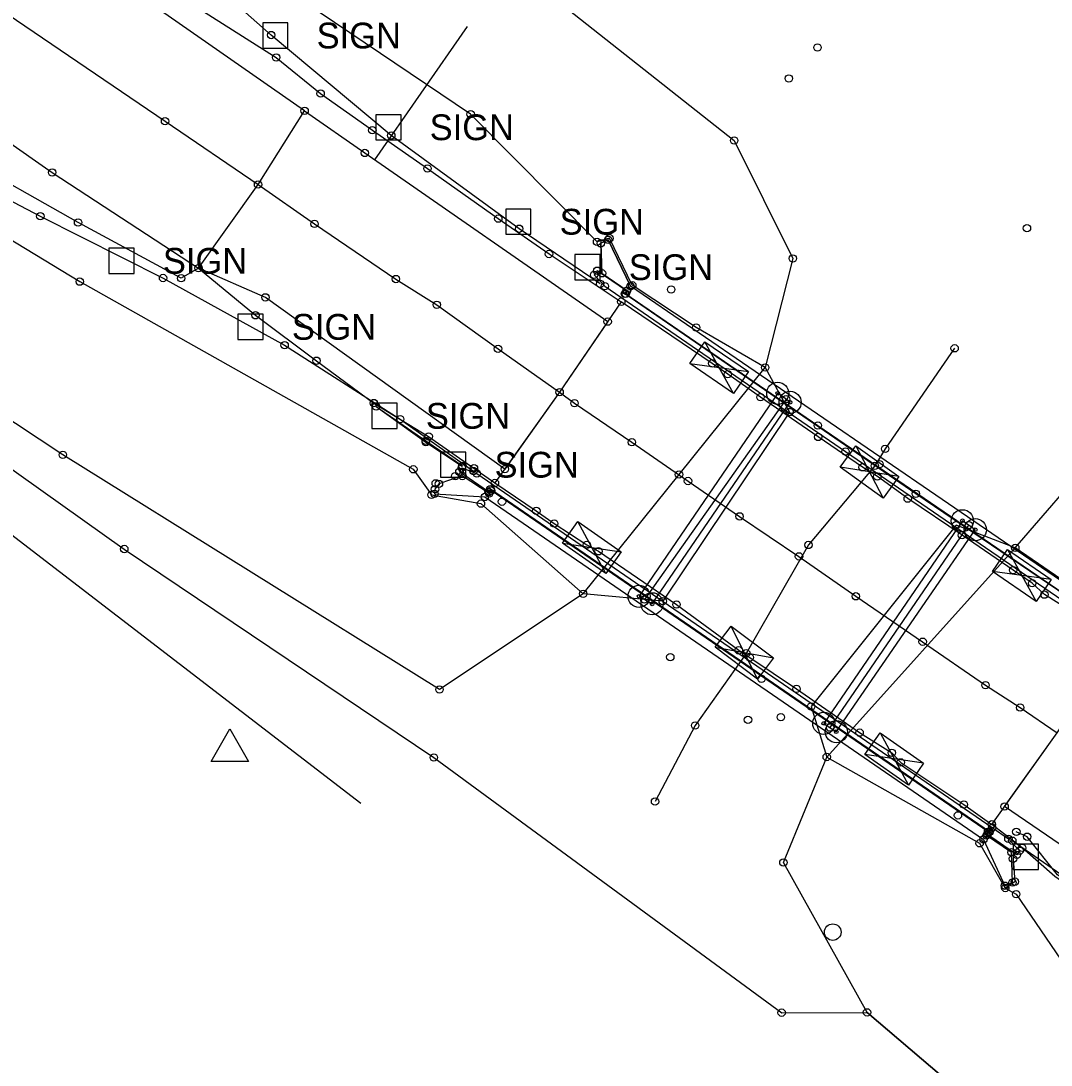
# Model space of a CAD drawing. Extents: x 15502398 to 15534190, y 8766930 to 8782112.
# Drawn here: x 15514814.8 to 15514954.6, y 8779044.6 to 8779186.3 of the extents above; entities that cross this region are included whole.
import ezdxf

# ---------------------------------------------------------------- set-up
doc = ezdxf.new("R2010")
doc.units = 0
for name, color, linetype in [('Bridge', 7, 'Continuous'), ('Default', 7, 'Continuous'), ('EXT_BL', 7, 'Continuous'), ('EXT_C', 7, 'Continuous'), ('EXT_CON', 7, 'Continuous'), ('EXT_CU', 7, 'Continuous'), ('EXT_D', 7, 'Continuous'), ('EXT_EP', 7, 'Continuous'), ('EXT_GU', 7, 'Continuous'), ('EXT_SH', 7, 'Continuous'), ('EXT_SNP', 7, 'Continuous'), ('Natural', 7, 'Continuous'), ('Roadways', 7, 'Continuous'), ('SurControl', 7, 'Continuous'), ('SurPointsNonDTM', 7, 'Continuous'), ('SurRoadPoints', 7, 'Continuous'), ('SurSurveyPoints', 7, 'Continuous'), ('SurUtilityStructureCell', 7, 'Continuous')]:
    doc.layers.add(name, color=color, linetype=linetype)

msp = doc.modelspace()

# ---------------------------------------------------------------- linework, layer by layer
at = {"layer": 'Bridge'}
for points in [[(15514968.75, 8779100.6), (15514969.07, 8779101.28), (15514971.97, 8779101.81), (15514972.1, 8779103.31), (15514965.17, 8779103.99), (15514897.53, 8779150.29), (15514894.5, 8779156.59), (15514893.48, 8779156.12), (15514893.65, 8779152.05), (15514897.07, 8779149.71), (15514896.88, 8779149.26), (15514922.95, 8779131.4), (15514964.36, 8779103.05), (15514964.63, 8779103.39)], [(15514968.68, 8779100.45), (15514964.72, 8779103.21), (15514964.5, 8779102.92), (15514936.22, 8779122.13), (15514896.74, 8779149.27), (15514896.98, 8779149.65), (15514892.99, 8779152.4), (15514892.59, 8779151.84), (15514894.03, 8779150.29), (15514926.69, 8779127.87), (15514966.4, 8779100.62), (15514968.22, 8779099.97)], [(15514949.95, 8779073.12), (15514945.97, 8779075.89), (15514946.23, 8779076.23), (15514878.5, 8779122.74), (15514878.27, 8779122.37), (15514874.3, 8779125.1), (15514874.64, 8779125.67), (15514876.68, 8779124.87), (15514946.6, 8779076.81), (15514948.79, 8779075.28), (15514950.32, 8779073.68)], [(15514949.36, 8779069.37), (15514949.21, 8779073.46), (15514945.82, 8779075.74), (15514946.03, 8779076.25), (15514878.6, 8779122.55), (15514878.34, 8779122.17), (15514874.7, 8779124.54), (15514871.53, 8779123.48), (15514870.99, 8779122.75), (15514870.92, 8779122.12), (15514877.75, 8779121.69), (15514945.42, 8779075.22), (15514948.31, 8779068.93)]]:
    msp.add_lwpolyline(points, close=True, dxfattribs=at)
at = {"layer": 'Default'}
for points in [[(15514893.39, 8779150.63), (15514882.42, 8779158.1), (15514865.06, 8779170.76), (15514848.76, 8779184.39), (15514828.98, 8779201.9)], [(15514805.39, 8779167.3), (15514804.8, 8779166.43), (15514817.44, 8779159.8), (15514834.09, 8779151.41), (15514850.59, 8779142.29), (15514866.26, 8779132.25), (15514876.21, 8779125.21)], [(15514960.76, 8779104.04), (15514953.68, 8779108.44), (15514952.01, 8779109.98), (15514949.45, 8779111.77), (15514942.5, 8779116.5), (15514935.13, 8779121.47), (15514931.01, 8779124.47), (15514929.01, 8779125.72), (15514922.98, 8779129.84), (15514915.15, 8779135.23), (15514910.73, 8779138.36), (15514908.62, 8779139.83), (15514896.27, 8779148.2), (15514887.9, 8779135.92), (15514879.13, 8779123.59)], [(15514887.9, 8779135.92), (15514889.92, 8779134.43), (15514897.71, 8779129.12), (15514905.32, 8779123.86), (15514912.32, 8779119.06), (15514920.38, 8779113.63), (15514928.09, 8779108.21), (15514937.16, 8779102.05), (15514945.69, 8779096.15), (15514950.38, 8779093.11), (15514955.43, 8779089.67)], [(15514918.63, 8779134.96), (15514899.4, 8779107.78)], [(15514876.28, 8779125.6), (15514879.13, 8779123.59), (15514884.74, 8779119.8), (15514887.17, 8779118.08), (15514891.59, 8779115.19), (15514893.17, 8779114.32), (15514903.77, 8779107.09), (15514912.2, 8779100.88), (15514913.72, 8779099.91), (15514920.05, 8779095.64), (15514928.61, 8779089.71), (15514932.97, 8779086.98), (15514934.18, 8779085.67), (15514942.74, 8779079.94), (15514946.55, 8779077.26), (15514955.43, 8779089.67)], [(15514924.6, 8779090.39), (15514943.43, 8779117.86)], [(15515014.78, 8779024.91), (15515014.27, 8779023.91), (15514993.78, 8779041.38), (15514983.04, 8779050.29), (15514963.22, 8779065.38), (15514949.32, 8779075.04)]]:
    msp.add_lwpolyline(points, dxfattribs=at)
for points in [[(15514900.45, 8779107.19), (15514919.18, 8779134.54), (15514917.5, 8779135.76), (15514898.68, 8779108.21)], [(15514944.3, 8779117.25), (15514942.55, 8779118.46), (15514923.75, 8779090.97), (15514925.44, 8779089.82)]]:
    msp.add_lwpolyline(points, close=True, dxfattribs=at)
at = {"layer": 'EXT_BL'}
for points in [[(15514603.51, 8779232.29), (15514601.83, 8779245.57), (15514595.97, 8779254.75), (15514571.89, 8779280.15), (15514580.49, 8779291.91), (15514600.21, 8779303.93), (15514639.34, 8779277.58), (15514691.14, 8779242.93), (15514735.8, 8779211.77), (15514779.77, 8779177.06), (15514822.79, 8779150.92), (15514868.05, 8779125.45), (15514870.51, 8779121.99), (15514877.23, 8779120.79), (15514891.1, 8779108.56)], [(15514891.1, 8779108.56), (15514871.59, 8779095.57), (15514820.49, 8779127.42), (15514785.11, 8779150.78), (15514725.93, 8779192.76), (15514674.35, 8779232.07), (15514625.56, 8779268.53), (15514604.03, 8779280.96), (15514600.16, 8779276.05), (15514595.07, 8779269.61), (15514606.22, 8779257.75), (15514613.46, 8779244.67), (15514610.28, 8779231.05)], [(15514797.21, 8779253.2), (15514839.32, 8779228.6), (15514874.17, 8779199.67), (15514911.58, 8779170.08), (15514919.55, 8779154.07), (15514915.79, 8779139.27), (15514906.42, 8779144.7), (15514897.76, 8779150.42), (15514894.68, 8779156.8), (15514892.98, 8779156.33), (15514875.83, 8779173.65), (15514853.31, 8779188.82), (15514802.74, 8779223.63)], [(15514941.5, 8779141.87), (15514932.06, 8779128.22), (15514930.67, 8779125.91), (15514921.66, 8779115.18), (15514913.23, 8779100.47), (15514906.3, 8779090.67), (15514900.85, 8779080.35)], [(15514891.1, 8779108.56), (15514904.1, 8779124.74), (15514915.79, 8779139.27)], [(15514915.79, 8779139.27), (15514919.11, 8779133.22), (15514901.89, 8779107.55), (15514891.1, 8779108.56)], [(15514972.37, 8779103.34), (15514965.29, 8779104.12), (15514949.73, 8779114.8), (15514960.51, 8779127.28), (15514971.69, 8779129.58), (15515012.98, 8779104.1), (15515039.09, 8779087.26), (15515084.34, 8779057.54), (15515121.87, 8779031.85), (15515136.34, 8779033.05), (15515158.53, 8779017.54), (15515157.87, 8778999.81), (15515198.39, 8778971.5), (15515237.86, 8778943.51), (15515264.4, 8778926.3), (15515290.1, 8778939.84)], [(15514949.73, 8779114.8), (15514941.69, 8779117.88), (15514922.03, 8779093.25), (15514924.14, 8779086.4)], [(15514924.14, 8779086.4), (15514949.73, 8779114.8)], [(15515236.34, 8778829.26), (15515147, 8778893.37), (15515095.71, 8778929.07), (15515036.69, 8778970.82), (15514983.06, 8779009.89), (15514945.58, 8779038.12), (15514929.61, 8779051.74), (15514918.26, 8779072.09), (15514924.14, 8779086.4)], [(15514924.14, 8779086.4), (15514944.89, 8779074.69), (15514948.37, 8779068.62), (15514949.86, 8779067.79), (15514955.86, 8779058.94), (15515004.6, 8779026.01), (15515051.74, 8778995.2), (15515103.32, 8778961.08), (15515168.39, 8778915.34), (15515228.98, 8778873.25), (15515256.8, 8778852.96)], [(15514949.42, 8779072.59), (15514949.68, 8779069.48), (15514948.37, 8779068.62)]]:
    msp.add_lwpolyline(points, dxfattribs=at)
at = {"layer": 'EXT_C'}
msp.add_lwpolyline([(15514539.01, 8779375.88), (15514557.84, 8779363.02), (15514577.62, 8779349.14), (15514597.39, 8779335.77), (15514617.16, 8779321.93), (15514638.22, 8779307.5), (15514657.64, 8779293.96), (15514678.58, 8779279.44), (15514697.02, 8779266.72), (15514717.08, 8779253.14), (15514730.81, 8779243.96), (15514754.17, 8779227.88), (15514774.39, 8779213.87), (15514794.54, 8779199.93), (15514814.21, 8779186.39), (15514834.36, 8779172.7), (15514846.98, 8779164.09), (15514854.64, 8779158.75), (15514865.69, 8779151.27), (15514871.23, 8779147.78), (15514879.54, 8779141.8), (15514887.9, 8779135.92)], dxfattribs=at)
at = {"layer": 'EXT_CON'}
for points in [[(15514893.65, 8779152.05), (15514893.48, 8779156.12), (15514894.5, 8779156.59), (15514897.53, 8779150.29)], [(15514874.7, 8779124.54), (15514871.53, 8779123.48), (15514870.99, 8779122.75), (15514870.92, 8779122.12), (15514877.75, 8779121.69)], [(15514945.42, 8779075.22), (15514948.31, 8779068.93), (15514949.36, 8779069.37), (15514949.21, 8779073.46)]]:
    msp.add_lwpolyline(points, dxfattribs=at)
at = {"layer": 'EXT_CU'}
for points in [[(15514863.02, 8779133.97), (15514869.76, 8779129.13), (15514874.67, 8779125.88)], [(15514962.8, 8779065.26), (15514961.63, 8779065.61), (15514955.09, 8779070.17), (15514950.65, 8779074.06), (15514946.55, 8779077.26)]]:
    msp.add_lwpolyline(points, dxfattribs=at)
at = {"layer": 'EXT_D'}
for p, q in [((15514642.88, 8779247.59), (15514860.95, 8779080.15)), ((15514862.83, 8779167.44), (15514875.41, 8779185.56))]:
    msp.add_line(p, q, dxfattribs=at)
at = {"layer": 'EXT_EP'}
for points in [[(15514853.3, 8779174.1), (15514834.8, 8779187), (15514799.88, 8779210.74), (15514777.73, 8779226.07), (15514758.94, 8779238.88), (15514760.07, 8779239.95)], [(15514798.13, 8779180.33), (15514819.06, 8779165.74), (15514838.9, 8779152.76)], [(15514838.9, 8779152.76), (15514846.63, 8779146.35), (15514854.91, 8779140.19), (15514862.7, 8779134.44), (15514870.13, 8779129.91), (15514879.13, 8779123.59)]]:
    msp.add_lwpolyline(points, dxfattribs=at)
at = {"layer": 'EXT_GU'}
for points in [[(15514863.02, 8779133.97), (15514869.73, 8779129.32), (15514874.72, 8779125.91), (15514874.67, 8779125.88)], [(15514962.8, 8779065.26), (15514962.15, 8779065.84), (15514955.44, 8779070.43), (15514951.34, 8779075.58), (15514949.87, 8779076.25)]]:
    msp.add_lwpolyline(points, dxfattribs=at)
at = {"layer": 'EXT_SH'}
msp.add_lwpolyline([(15514809.56, 8779207.33), (15514816.96, 8779202.78), (15514833.52, 8779191.48), (15514849.45, 8779181.35), (15514855.47, 8779176.44), (15514862.49, 8779171.48), (15514869.96, 8779166.28), (15514879.58, 8779159.47), (15514886.46, 8779154.67), (15514896.27, 8779148.2)], dxfattribs=at)
at = {"layer": 'EXT_SNP'}
msp.add_lwpolyline([(15514838.9, 8779152.76), (15514836.55, 8779151.38), (15514822.56, 8779158.95), (15514806.37, 8779168.08), (15514787.02, 8779180.21), (15514762.57, 8779195.1), (15514715.8, 8779227.37), (15514667.65, 8779260.24), (15514628.46, 8779287.04), (15514585.22, 8779314.14)], dxfattribs=at)
at = {"layer": 'Natural'}
msp.add_lwpolyline([(15514714.5, 8779119.23), (15514742.47, 8779138.72), (15514734.07, 8779166.12), (15514775.23, 8779152.76), (15514828.83, 8779114.63), (15514870.83, 8779086.34), (15514918.03, 8779051.7), (15514929.61, 8779051.74), (15514945.58, 8779038.12), (15514983.06, 8779009.89), (15515036.69, 8778970.82), (15515087.59, 8778922.26), (15515066.58, 8778890.05)], dxfattribs=at)
at = {"layer": 'Roadways'}
for points in [[(15514894.42, 8779145.49), (15514887.9, 8779135.92), (15514880.47, 8779125.48), (15514847.98, 8779148.78), (15514838.9, 8779152.76), (15514846.98, 8779164.09), (15514853.3, 8779174.1), (15514861.47, 8779168.38)], [(15515004, 8779071.19), (15514996.44, 8779061.55), (15514989.57, 8779051.49), (15514981.33, 8779057.12), (15514948.28, 8779079.67), (15514955.43, 8779089.67), (15514961.79, 8779099.09), (15514994.98, 8779076.8)]]:
    msp.add_lwpolyline(points, close=True, dxfattribs=at)
at = {"layer": 'SurControl'}
msp.add_lwpolyline([(15514843.16, 8779090.22), (15514845.7, 8779085.81), (15514840.61, 8779085.81)], close=True, dxfattribs=at)
msp.add_circle((15514924.96, 8779062.63), 1.12, dxfattribs=at)
at = {"layer": 'SurPointsNonDTM'}
for centre in [(15514848.76, 8779184.39), (15514853.3, 8779174.1), (15514865.06, 8779170.76), (15514861.47, 8779168.38), (15514846.98, 8779164.09), (15514817.44, 8779159.8), (15514882.42, 8779158.1), (15514893.48, 8779156.12), (15514894.5, 8779156.59), (15514838.9, 8779152.76), (15514892.59, 8779151.84), (15514892.99, 8779152.4), (15514893.65, 8779152.05), (15514834.09, 8779151.41), (15514893.39, 8779150.63), (15514894.03, 8779150.29), (15514897.53, 8779150.29), (15514847.98, 8779148.78), (15514896.74, 8779149.27), (15514896.88, 8779149.26), (15514896.98, 8779149.65), (15514897.07, 8779149.71), (15514903.03, 8779149.86), (15514896.27, 8779148.2), (15514894.42, 8779145.49), (15514894.42, 8779145.49), (15514850.59, 8779142.29), (15514908.62, 8779139.83), (15514910.73, 8779138.36), (15514887.9, 8779135.92), (15514887.9, 8779135.92), (15514887.9, 8779135.92), (15514915.15, 8779135.23), (15514918.63, 8779134.96), (15514889.92, 8779134.43), (15514866.26, 8779132.25), (15514922.95, 8779131.4), (15514897.71, 8779129.12), (15514922.98, 8779129.84), (15514926.69, 8779127.87), (15514931.31, 8779126.15), (15514874.3, 8779125.1), (15514874.64, 8779125.67), (15514876.21, 8779125.21), (15514876.28, 8779125.6), (15514876.68, 8779124.87), (15514880.47, 8779125.48), (15514929.01, 8779125.72), (15514871.53, 8779123.48), (15514874.7, 8779124.54), (15514879.13, 8779123.59), (15514879.13, 8779123.59), (15514905.32, 8779123.86), (15514931.01, 8779124.47), (15514870.92, 8779122.12), (15514870.99, 8779122.75), (15514878.27, 8779122.37), (15514878.34, 8779122.17), (15514878.5, 8779122.74), (15514878.6, 8779122.55), (15514936.22, 8779122.13), (15514877.75, 8779121.69), (15514880.08, 8779121.05), (15514935.13, 8779121.47), (15514884.74, 8779119.8), (15514912.32, 8779119.06), (15514887.17, 8779118.08), (15514943.43, 8779117.86), (15514942.5, 8779116.5), (15514891.59, 8779115.19), (15514828.83, 8779114.63), (15514893.17, 8779114.32), (15514920.38, 8779113.63), (15514949.45, 8779111.77), (15514952.01, 8779109.98), (15514899.4, 8779107.78), (15514928.09, 8779108.21), (15514953.68, 8779108.44), (15514903.77, 8779107.09), (15514937.16, 8779102.05), (15514912.2, 8779100.88), (15514913.72, 8779099.91), (15514915.28, 8779097.01), (15514920.05, 8779095.64), (15514945.69, 8779096.15), (15514950.38, 8779093.11), (15514924.6, 8779090.39), (15514928.61, 8779089.71), (15514870.83, 8779086.34), (15514932.97, 8779086.98), (15514934.18, 8779085.67), (15514942.74, 8779079.94), (15514948.28, 8779079.67), (15514941.95, 8779078.48), (15514946.55, 8779077.26), (15514946.6, 8779076.81), (15514945.42, 8779075.22), (15514945.82, 8779075.74), (15514945.97, 8779075.89), (15514946.03, 8779076.25), (15514946.23, 8779076.23), (15514948.79, 8779075.28), (15514949.32, 8779075.04), (15514950.32, 8779073.68), (15514949.21, 8779073.46), (15514949.95, 8779073.12), (15514949.95, 8779073.12), (15514949.36, 8779069.37), (15514949.36, 8779069.37), (15514948.31, 8779068.93), (15514918.03, 8779051.7), (15514929.61, 8779051.74)]:
    msp.add_circle(centre, 0.5, dxfattribs=at)
at = {"layer": 'SurRoadPoints'}
for points in [[(15514849.33, 8779182.61), (15514849.33, 8779182.61), (15514851.04, 8779182.61), (15514851.04, 8779186.03), (15514847.62, 8779186.03), (15514847.62, 8779182.61), (15514849.33, 8779182.61)], [(15514864.66, 8779170.16), (15514864.66, 8779170.16), (15514866.38, 8779170.16), (15514866.38, 8779173.58), (15514862.95, 8779173.58), (15514862.95, 8779170.16), (15514864.66, 8779170.16)], [(15514882.3, 8779157.34), (15514882.3, 8779157.34), (15514884.01, 8779157.34), (15514884.01, 8779160.76), (15514880.59, 8779160.76), (15514880.59, 8779157.34), (15514882.3, 8779157.34)], [(15514828.46, 8779152.02), (15514828.46, 8779152.02), (15514830.17, 8779152.02), (15514830.17, 8779155.45), (15514826.75, 8779155.45), (15514826.75, 8779152.02), (15514828.46, 8779152.02)], [(15514891.68, 8779151.16), (15514891.68, 8779151.16), (15514893.39, 8779151.16), (15514893.39, 8779154.59), (15514889.97, 8779154.59), (15514889.97, 8779151.16), (15514891.68, 8779151.16)], [(15514845.96, 8779143.07), (15514845.96, 8779143.07), (15514847.68, 8779143.07), (15514847.68, 8779146.5), (15514844.25, 8779146.5), (15514844.25, 8779143.07), (15514845.96, 8779143.07)], [(15514864.14, 8779130.98), (15514864.14, 8779130.98), (15514865.86, 8779130.98), (15514865.86, 8779134.41), (15514862.43, 8779134.41), (15514862.43, 8779130.98), (15514864.14, 8779130.98)], [(15514873.46, 8779124.36), (15514873.46, 8779124.36), (15514875.17, 8779124.36), (15514875.17, 8779127.79), (15514871.75, 8779127.79), (15514871.75, 8779124.36), (15514873.46, 8779124.36)], [(15514951.15, 8779071.14), (15514951.15, 8779071.14), (15514952.87, 8779071.14), (15514952.87, 8779074.57), (15514949.44, 8779074.57), (15514949.44, 8779071.14), (15514951.15, 8779071.14)]]:
    msp.add_lwpolyline(points, dxfattribs=at)
for centre, radius in [((15514917.5, 8779135.76), 1.5), ((15514917.5, 8779135.76), 0.25), ((15514919.18, 8779134.54), 1.5), ((15514919.18, 8779134.54), 0.25), ((15514942.55, 8779118.46), 1.5), ((15514942.55, 8779118.46), 0.25), ((15514944.3, 8779117.25), 1.5), ((15514944.3, 8779117.25), 1.5), ((15514944.3, 8779117.25), 0.25), ((15514944.3, 8779117.25), 0.25), ((15514898.68, 8779108.21), 1.5), ((15514898.68, 8779108.21), 0.25), ((15514900.45, 8779107.19), 1.5), ((15514900.45, 8779107.19), 1.5), ((15514900.45, 8779107.19), 0.25), ((15514900.45, 8779107.19), 0.25), ((15514923.75, 8779090.97), 1.5), ((15514923.75, 8779090.97), 0.25), ((15514925.44, 8779089.82), 1.5), ((15514925.44, 8779089.82), 0.25)]:
    msp.add_circle(centre, radius, dxfattribs=at)
at = {"layer": 'SurSurveyPoints'}
for centre in [(15514849.45, 8779181.35), (15514922.9, 8779182.69), (15514919, 8779178.5), (15514855.47, 8779176.44), (15514853.3, 8779174.1), (15514875.83, 8779173.65), (15514834.36, 8779172.7), (15514862.49, 8779171.48), (15514911.58, 8779170.08), (15514819.06, 8779165.74), (15514869.96, 8779166.28), (15514846.98, 8779164.09), (15514822.56, 8779158.95), (15514854.64, 8779158.75), (15514879.58, 8779159.47), (15514951.31, 8779158.17), (15514892.98, 8779156.33), (15514893.48, 8779156.12), (15514894.5, 8779156.59), (15514894.68, 8779156.8), (15514886.46, 8779154.67), (15514919.55, 8779154.07), (15514838.9, 8779152.76), (15514838.9, 8779152.76), (15514838.9, 8779152.76), (15514893.65, 8779152.05), (15514822.79, 8779150.92), (15514836.55, 8779151.38), (15514865.69, 8779151.27), (15514897.53, 8779150.29), (15514897.76, 8779150.42), (15514871.23, 8779147.78), (15514896.27, 8779148.2), (15514846.63, 8779146.35), (15514906.42, 8779144.7), (15514879.54, 8779141.8), (15514941.5, 8779141.87), (15514854.91, 8779140.19), (15514915.79, 8779139.27), (15514915.79, 8779139.27), (15514915.79, 8779139.27), (15514887.9, 8779135.92), (15514862.7, 8779134.44), (15514863.02, 8779133.97), (15514863.02, 8779133.97), (15514919.11, 8779133.22), (15514869.73, 8779129.32), (15514869.76, 8779129.13), (15514870.13, 8779129.91), (15514932.06, 8779128.22), (15514820.49, 8779127.42), (15514868.05, 8779125.45), (15514874.67, 8779125.88), (15514874.67, 8779125.88), (15514874.72, 8779125.91), (15514904.1, 8779124.74), (15514930.67, 8779125.91), (15514871.09, 8779123.54), (15514871.53, 8779123.48), (15514873.74, 8779124.52), (15514874.7, 8779124.54), (15514879.13, 8779123.59), (15514870.51, 8779121.99), (15514870.92, 8779122.12), (15514870.99, 8779122.75), (15514877.23, 8779120.79), (15514877.75, 8779121.69), (15514941.69, 8779117.88), (15514921.66, 8779115.18), (15514949.73, 8779114.8), (15514949.73, 8779114.8), (15514949.73, 8779114.8), (15514891.1, 8779108.56), (15514891.1, 8779108.56), (15514891.1, 8779108.56), (15514891.1, 8779108.56), (15514901.89, 8779107.55), (15514902.92, 8779099.96), (15514913.23, 8779100.47), (15514871.59, 8779095.57), (15514922.03, 8779093.25), (15514906.3, 8779090.67), (15514913.46, 8779091.45), (15514917.93, 8779091.81), (15514924.14, 8779086.4), (15514924.14, 8779086.4), (15514924.14, 8779086.4), (15514924.14, 8779086.4), (15514900.85, 8779080.35), (15514946.55, 8779077.26), (15514945.42, 8779075.22), (15514949.87, 8779076.25), (15514951.34, 8779075.58), (15514944.89, 8779074.69), (15514950.65, 8779074.06), (15514949.21, 8779073.46), (15514949.42, 8779072.59), (15514918.26, 8779072.09), (15514949.36, 8779069.37), (15514949.68, 8779069.48), (15514948.31, 8779068.93), (15514948.37, 8779068.62), (15514948.37, 8779068.62), (15514949.86, 8779067.79), (15514929.61, 8779051.74)]:
    msp.add_circle(centre, 0.5, dxfattribs=at)
at = {"layer": 'SurUtilityStructureCell'}
for points in [[(15514905.57, 8779139.81), (15514907.61, 8779142.77), (15514913.54, 8779138.7), (15514911.5, 8779135.73)], [(15514933.91, 8779124.45), (15514931.81, 8779121.53), (15514925.97, 8779125.73), (15514928.07, 8779128.65)], [(15514888.28, 8779115.41), (15514890.35, 8779118.36), (15514896.24, 8779114.24), (15514894.18, 8779111.29)], [(15514954.58, 8779110.48), (15514952.55, 8779107.51), (15514946.62, 8779111.59), (15514948.65, 8779114.55)], [(15514909.02, 8779101.31), (15514911.19, 8779104.18), (15514916.93, 8779099.84), (15514914.76, 8779096.97)], [(15514937.28, 8779085.55), (15514935.22, 8779082.6), (15514929.33, 8779086.72), (15514931.39, 8779089.67)]]:
    msp.add_lwpolyline(points, close=True, dxfattribs=at)
for points in [[(15514905.57, 8779139.81), (15514913.54, 8779138.7), (15514911.5, 8779135.73), (15514907.61, 8779142.77)], [(15514933.91, 8779124.45), (15514925.97, 8779125.73), (15514928.07, 8779128.65), (15514931.81, 8779121.53)], [(15514888.28, 8779115.41), (15514896.24, 8779114.24), (15514894.18, 8779111.29), (15514890.35, 8779118.36)], [(15514954.58, 8779110.48), (15514946.62, 8779111.59), (15514948.65, 8779114.55), (15514952.55, 8779107.51)], [(15514909.02, 8779101.31), (15514916.93, 8779099.84), (15514914.76, 8779096.97), (15514911.19, 8779104.18)], [(15514937.28, 8779085.55), (15514929.33, 8779086.72), (15514931.39, 8779089.67), (15514935.22, 8779082.6)]]:
    msp.add_lwpolyline(points, dxfattribs=at)

# ---------------------------------------------------------------- texts
at = {"layer": 'SurRoadPoints'}
for p in [(15514854.93, 8779182.57), (15514870.27, 8779170.12), (15514887.91, 8779157.3), (15514834.07, 8779151.99), (15514897.29, 8779151.13), (15514851.57, 8779143.03), (15514869.75, 8779130.95), (15514879.07, 8779124.32)]:
    msp.add_text('SIGN', height=3.498, dxfattribs=at).set_placement(p)

doc.saveas('drawing.dxf')
